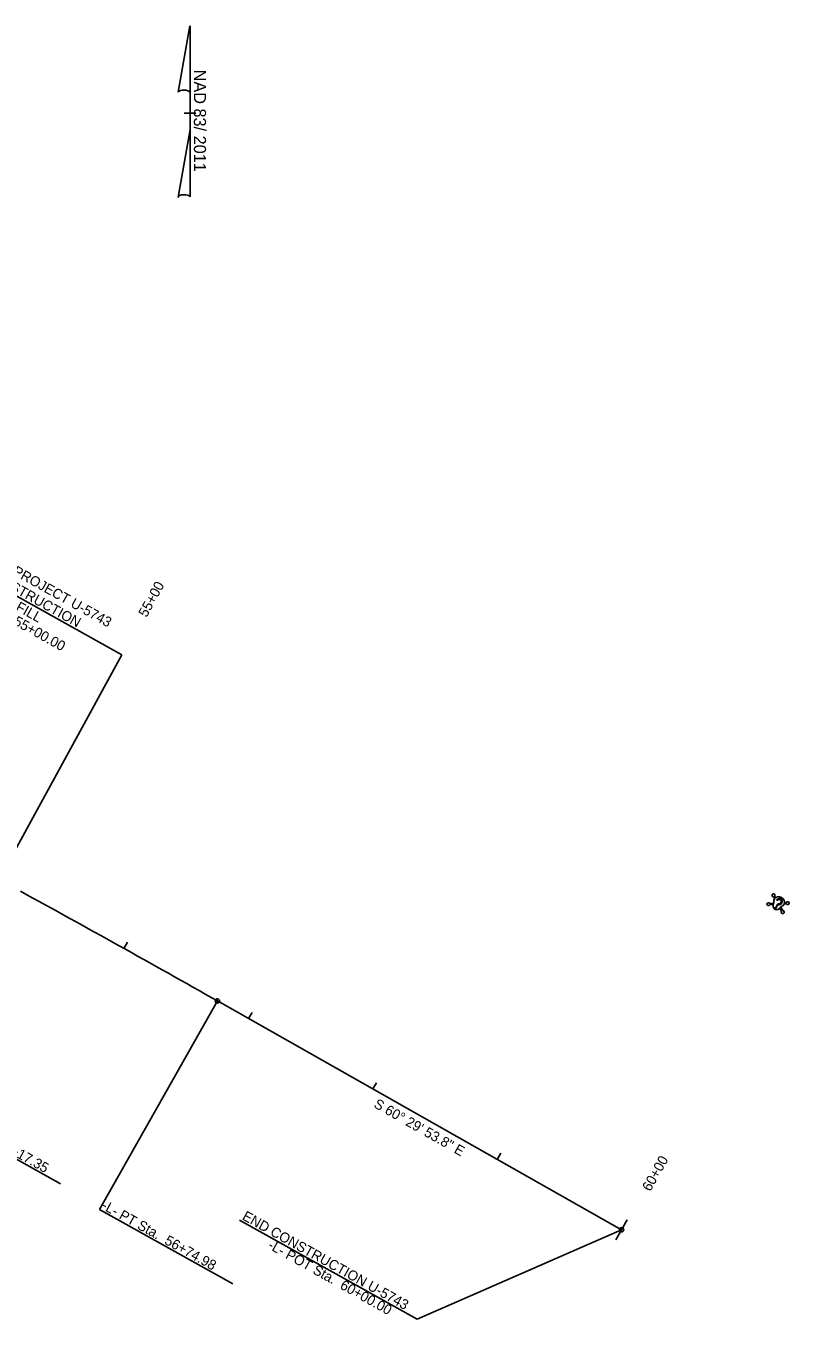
# Model space of a CAD drawing. Extents: x 1762196 to 1766326, y 709922 to 713142.
# Drawn here: x 1765792 to 1766326, y 709995 to 710900 of the extents above; entities that cross this region are included whole.
import ezdxf

# ---------------------------------------------------------------- set-up
doc = ezdxf.new("R2010")
doc.units = 0
for name, color, linetype in [('Prop Dimension', 7, 'Continuous'), ('Prop Horizontal Alignment', 7, 'Continuous'), ('Prop Horizontal Alignment Direction Label', 7, 'Continuous'), ('Prop Horizontal Alignment Station Label', 7, 'Continuous'), ('Prop Horizontal Alignment Tick Label', 7, 'Continuous'), ('Prop Horizontal Alignment Tick Large', 7, 'Continuous'), ('Prop Horizontal Alignment Tick Small', 7, 'Continuous'), ('Prop North Arrow NAD83 for Plan Sheets CELL', 7, 'Continuous')]:
    doc.layers.add(name, color=color, linetype=linetype)

msp = doc.modelspace()

# ---------------------------------------------------------------- linework, layer by layer
at = {"layer": 'Prop Dimension'}
for p, q in [((1766315.19, 710290.86), (1766315.93, 710289.5)), ((1766316.04, 710291.33), (1766316.64, 710290.23)), ((1766315.27, 710286.32), (1766312.57, 710286.18)), ((1766314.97, 710285.33), (1766312.62, 710285.2)), ((1766317.53, 710285.05), (1766317.26, 710284.58)), ((1766317.26, 710284.58), (1766317.8, 710284.28)), ((1766317.6, 710285.01), (1766317.34, 710284.53)), ((1766317.68, 710284.97), (1766317.42, 710284.49)), ((1766317.47, 710288.44), (1766318.01, 710288.14)), ((1766317.76, 710284.92), (1766317.49, 710284.45)), ((1766317.84, 710284.88), (1766317.57, 710284.4)), ((1766317.91, 710284.84), (1766317.65, 710284.36)), ((1766317.99, 710284.79), (1766317.72, 710284.32)), ((1766318.07, 710284.75), (1766317.8, 710284.28)), ((1766318.56, 710286.27), (1766318.56, 710286.27)), ((1766319.64, 710282.72), (1766320.77, 710280.66)), ((1766320.33, 710283.5), (1766321.63, 710281.13)), ((1766324.24, 710285.81), (1766322.69, 710285.73)), ((1766324.19, 710286.79), (1766322.94, 710286.72))]:
    msp.add_line(p, q, dxfattribs=at)
for radius in [0.443, 0.345, 0.244, 0.146, 0.0472]:
    msp.add_circle((1766316.89, 710283.24), radius, dxfattribs=at)
for centre, start, end in [((1766315.17, 710291.9), 326.74936, 270.65791), ((1766311.68, 710285.64), 31.04557, 334.95413), ((1766321.64, 710280.09), 146.74936, 90.65791), ((1766325.13, 710286.35), 211.04557, 154.95413)]:
    msp.add_arc(centre, 1.04, start, end, dxfattribs=at)
for centre, major_axis, ratio, start_param, end_param in [((1766319.16, 710287.35), (3.4, -1.89), 0.885014, 5.564242, 10.143721), ((1766319.22, 710287.46), (1.09, 1.95), 0.9, 3.567618, 7.853982), ((1766319.22, 710287.46), (1.04, 1.86), 0.9, 3.567618, 7.853982), ((1766319.22, 710287.46), (0.99, 1.78), 0.9, 3.567618, 7.853982), ((1766319.22, 710287.46), (0.94, 1.69), 0.9, 3.567618, 7.853982), ((1766319.22, 710287.46), (0.9, 1.6), 0.9, 3.567618, 7.853982), ((1766319.22, 710287.46), (0.85, 1.52), 0.9, 3.567618, 7.853982), ((1766318.08, 710285.4), (-1.89, -3.4), 0.752542, 4.722735, 7.843636), ((1766318.84, 710284.32), (0.82, 1.46), 0.9, 0.426026, 1.570796), ((1766318.84, 710284.32), (0.77, 1.38), 0.9, 0.426026, 1.570796), ((1766318.84, 710284.32), (0.72, 1.29), 0.9, 0.426026, 1.570796), ((1766318.84, 710284.32), (0.67, 1.2), 0.9, 0.426026, 1.570796), ((1766318.84, 710284.32), (0.62, 1.12), 0.9, 0.426026, 1.570796), ((1766318.84, 710284.32), (0.58, 1.03), 0.9, 0.426026, 1.570796), ((1766319.22, 710287.46), (0.8, 1.43), 0.9, 3.567618, 7.853982), ((1766318.84, 710284.32), (0.527, 0.946), 0.9, 0.426026, 1.570796), ((1766319.22, 710287.46), (0.75, 1.35), 0.9, 3.567618, 7.853982), ((1766318.84, 710284.32), (0.479, 0.86), 0.9, 0.426026, 1.570796)]:
    msp.add_ellipse(centre, major_axis=major_axis, ratio=ratio, start_param=start_param, end_param=end_param, dxfattribs=at)
at = {"layer": 'Prop Horizontal Alignment'}
msp.add_line((1765925.98, 710217.97), (1766208.86, 710057.91), dxfattribs=at)
msp.add_arc((1760282.51, 700243.86), 11460, 60.49827, 61.286353, dxfattribs=at)
at = {"layer": 'Prop Horizontal Alignment Station Label'}
for p, q in [((1765741.89, 710525.28), (1765859.08, 710460.02)), ((1765859.08, 710460.02), (1765773.05, 710302.98)), ((1765925.98, 710217.97), (1765843.47, 710072.13)), ((1765725.38, 710140.71), (1765816.18, 710090.15)), ((1765843.47, 710072.13), (1765936.78, 710020.16)), ((1765941.51, 710064.71), (1766065.91, 709995.43)), ((1766208.86, 710057.91), (1766065.91, 709995.43))]:
    msp.add_line(p, q, dxfattribs=at)
for centre in [(1765925.98, 710217.97), (1766208.86, 710057.91)]:
    msp.add_circle(centre, 1.5, dxfattribs=at)
at = {"layer": 'Prop Horizontal Alignment Tick Large'}
for q in [(1766212.8, 710064.87), (1766212.8, 710064.87), (1766204.92, 710050.95), (1766204.92, 710050.95)]:
    msp.add_line((1766208.86, 710057.91), q, dxfattribs=at)
at = {"layer": 'Prop Horizontal Alignment Tick Small'}
for p, q in [((1765860.61, 710254.68), (1765863.04, 710259.04)), ((1765860.61, 710254.68), (1765863.04, 710259.04)), ((1765947.76, 710205.64), (1765950.22, 710210)), ((1765947.76, 710205.64), (1765950.22, 710210)), ((1766034.8, 710156.4), (1766037.26, 710160.75)), ((1766034.8, 710156.4), (1766037.26, 710160.75)), ((1766121.83, 710107.15), (1766124.29, 710111.51)), ((1766121.83, 710107.15), (1766124.29, 710111.51))]:
    msp.add_line(p, q, dxfattribs=at)
at = {"layer": 'Prop North Arrow NAD83 for Plan Sheets CELL'}
for p, q in [((1765898.57, 710853.58), (1765906.77, 710899.93)), ((1765906.82, 710899.93), (1765906.82, 710852.13)), ((1765906.82, 710827.33), (1765906.82, 710853.53)), ((1765906.82, 710852.13), (1765906.82, 710853.48)), ((1765902.82, 710838.93), (1765902.77, 710838.93)), ((1765906.37, 710838.93), (1765902.82, 710838.93)), ((1765902.87, 710838.93), (1765910.87, 710838.93)), ((1765906.82, 710827.33), (1765898.47, 710780.08)), ((1765906.87, 710780.28), (1765906.82, 710827.33))]:
    msp.add_line(p, q, dxfattribs=at)
for centre, start_param, end_param in [((1765902.71, 710853.08), 0.216388, 2.908219), ((1765902.71, 710779.91), 0.201328, 3.141593)]:
    msp.add_ellipse(centre, major_axis=(4.23, -0.03), ratio=0.461098, start_param=start_param, end_param=end_param, dxfattribs=at)

# ---------------------------------------------------------------- texts
at = {"layer": 'Prop Horizontal Alignment Direction Label'}
msp.add_text('S 60%%d 29\' 53.8" E', height=7, rotation=330.49827, dxfattribs=at).set_placement((1766034.86, 710143.95))
at = {"layer": 'Prop Horizontal Alignment Station Label'}
for s, p in [('END TIP PROJECT U-5743', (1765747.68, 710535.76)), ('END CONSTRUCTION', (1765742.57, 710526.58)), ('END MILL & FILL', (1765736.57, 710518.1)), ('-L- POT Sta.  55+00.00', (1765732.31, 710509.57)), ('-L- PC Sta.  55+17.35', (1765726.12, 710141.58)), ('-L- PT Sta.  56+74.98', (1765844.32, 710072.95)), ('END CONSTRUCTION U-5743', (1765942.8, 710065.41)), ('-L- POT Sta.  60+00.00', (1765960.79, 710045.24))]:
    msp.add_text(s, height=7, rotation=330.88754, dxfattribs=at).set_placement(p)
at = {"layer": 'Prop Horizontal Alignment Tick Label'}
for s, rotation, p in [('55+00', 61.28635, (1765876.46, 710485.81)), ('60+00', 60.49827, (1766228.94, 710084.26))]:
    msp.add_text(s, height=7, rotation=rotation, dxfattribs=at).set_placement(p)
at = {"layer": 'Prop North Arrow NAD83 for Plan Sheets CELL'}
msp.add_text('NAD 83/ 2011', height=8.5, rotation=270, dxfattribs=at).set_placement((1765909.53, 710869.28))

doc.saveas('drawing.dxf')
